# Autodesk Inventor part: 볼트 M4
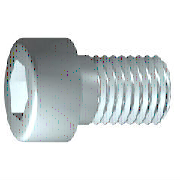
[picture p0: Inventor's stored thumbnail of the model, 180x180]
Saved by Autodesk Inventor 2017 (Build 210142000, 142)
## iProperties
IsCustomPart: 0
Created: 2018-09
Part Number: 볼트 M4
Material: 스테인리스강
Description: 6각머리 태핑 나사
Document SubType Name: Modeling
Standard: KS B 1003
Standards Organization: KS
Language: ko-KR
Size Designation: M 4 x 10
Categories: <MemberInstance><Categories><Category DisplayName="조임쇠" InternalName="e4da775c-781d-43d5-af7c-5136215cf5a6" Mnemonic="FSTN"><Category DisplayName="볼트" InternalN
Density: 8.08 g/cm^3
Mass: 2.09412 g
Surface Area: 3.0572 cm^2
Volume: 0.259174 cm^3
Appearance: 반광택
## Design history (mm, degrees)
sketch "스케치1"
  geometry: L1 (-1, 0)-(10, 0); L2 (10, 0)-(10, 2); L3 (10, 2)-(1.75, 2); L4 (1.75, 2)-(1.32, 2); L5 (1.32, 2)-(0, 2); L6 (0, 2)-(0, 3.5); L7 (0, 3.5)-(-4, 3.5); L8 (-4, 3.5)-(-4, 1.732); L9 (-4, 1.732)-(-2, 1.732); L10 (-2, 1.732)-(-1, 0); L11 (-6.8, 0)-(12.8, 0) reference; L12 (0, -0.7)-(0, 4.2) reference; L13 (1.75, 2)-(0, 2)
  constraints: 22 end point, 6 parallel, 2 collinear, 2 perpendicular, 1 horizontal, 1 point on line
  dimensions: "d1" = 8.25 distance from line of L3.end L2 (= GEL); "d2" = 0.42952 distance of L4.end L3.end (computed from GAL); "d3" = 4 distance between parallel lines of L8 L6 (= KOH); "d4" = 2 distance of L8.end L9.end (= INTI); "d5" = 60 deg angle of L10 L1; "d6" = 4 diameter of L3 L1 (= GD); "d7" = 4 diameter of L5 L1 (= BDM); "d8" = 3.4641 diameter of L9 L1 (= 1.1547 x SW); "d9" = 7 diameter of L7 L1 (= KOD); "d26" = 10 distance between parallel lines of L12 L2 (= NLG)
revolve "본체" sketch "스케치1" stored, may be unused: angle "d10" = 90 deg
sketch "스케치2"
  geometry: L1 (0, -4.9)-(0, 4.9) reference; L2 (-4.9, 0)-(4.9, 0) reference; L3 (1.732, 0)-(0.866, -1.5); L4 (0.866, -1.5)-(-0.866, -1.5); L5 (-0.866, -1.5)-(-1.732, 0); L6 (-1.732, 0)-(-0.866, 1.5); L7 (-0.866, 1.5)-(0.866, 1.5); L8 (0.866, 1.5)-(1.732, 0); 2 further points
  constraints: 12 end point, 1 coincident, 1 horizontal alignment, 1 point on line, 12 other
extrude "슬롯" join sketch "스케치2" stored distance "d11" = 10; taper "d12" = 0 deg
workplane "Work Plane1"
fillet "Fillet2" dims "d30" = 0.1 (= R)
body "Solid1"
fillet "모깎기1" dims "d17" = 0.4 (= RR)
feature "스레드" dims "d13" = 8.25 (= GEL), "d14" = 0
chamfer "모따기1" distance "d15" = 0.42941 (= -0.5 x SPD + 0.5 x GD); stored, may be unused: second distance "d16" = 0.42941 (= GUL), angle "d27" = 45 deg
other parameters: "GD" = 4 (= NND) [user parameter; used in 2 equation terms], "NLG" = 10 [user parameter; used in 1 equation term], "GEL" = 8.25 [user parameter; used in 2 equation terms], "KOD" = 7 [user parameter; used in 1 equation term], "KOH" = 4 [user parameter; used in 1 equation term], "INTI" = 2 [user parameter; used in 1 equation term], "GAL" = 0.42941 (= 0.61345 x PTC) [user parameter; used in 1 equation term], "GUL" = 0.42941 (= 0.61345 x PTC) [user parameter; used in 1 equation term], "BDM" = 4 (= NND) [user parameter; used in 1 equation term], "SW" = 3 [user parameter; used in 2 equation terms], "RR" = 0.4 [user parameter; used in 1 equation term], "SPD" = 3.14117 (= NND - 1.2269 x PTC) [user parameter; used in 1 equation term], "d19" = 0, "d28" = 0, "d29" = 0, "R" = 0.1 [user parameter; used in 1 equation term], "PHH" = 0.2 [user parameter], "GD1" = 3.14117 (= THREADDIA - 1.2269 x PTC) [user parameter], "THREADDIA" = 4 [user parameter; used in 1 equation term], "FAWI" = 45 deg [user parameter], "TPU" = 14.28571 (computed from PTC) [user parameter], "PTC" = 0.7 [user parameter; used in 5 equation terms], "NND" = 4 [user parameter; used in 3 equation terms], "TOA" = 30 deg [user parameter], "E0" = 3.465 (= 1.155 x SW) [user parameter]
